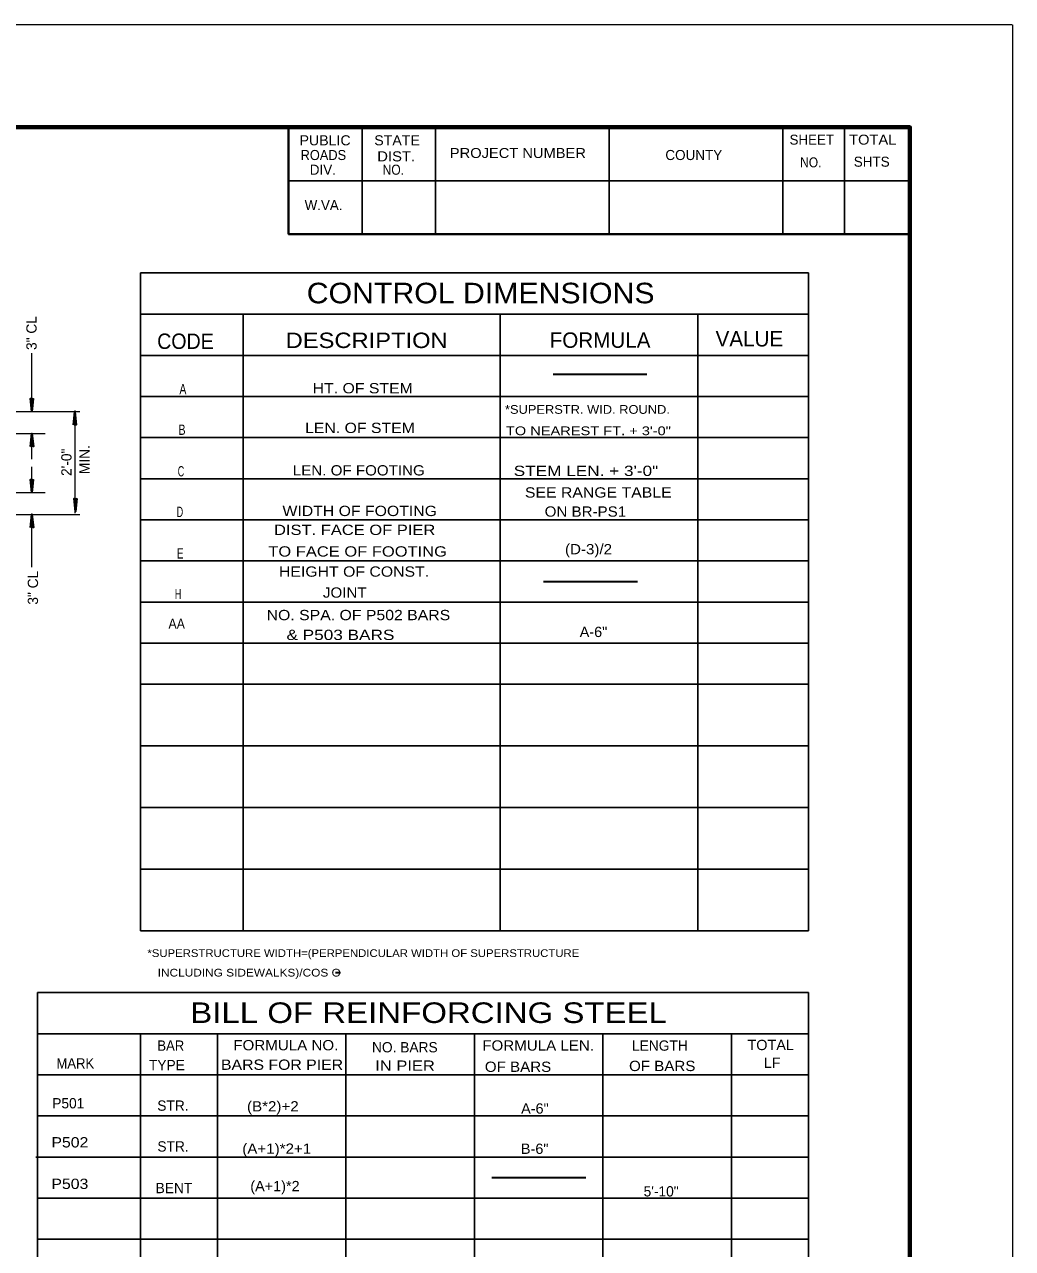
# Model space of a CAD drawing. Extents: x 4.49 to 7.69, y 0.28 to 2.27.
# Drawn here: x 6.888 to 7.689, y 1.277 to 2.269 of the extents above; entities that cross this region are included whole.
import ezdxf
from ezdxf.enums import TextEntityAlignment as Align

# ---------------------------------------------------------------- set-up
doc = ezdxf.new("R2010")
doc.units = 0
doc.header["$LTSCALE"] = 0.0033
doc.layers.add('1', color=7, linetype='Continuous', lineweight=35)

msp = doc.modelspace()

# ---------------------------------------------------------------- linework, layer by layer
at = {"layer": '1', "lineweight": 13}
for p, q in [((4.492417, 2.2695), (7.688833, 2.2695)), ((7.689083, 2.269333), (7.689083, 0.282917)), ((6.894083, 1.9655), (6.894083, 2.002917)), ((6.853333, 1.955583), (6.932833, 1.955583)), ((6.928833, 1.956583), (6.928833, 1.87325)), ((6.834917, 1.937917), (6.90475, 1.937917)), ((6.894083, 1.917), (6.894083, 1.937833)), ((6.894083, 1.889917), (6.894083, 1.91075)), ((6.83475, 1.889917), (6.90475, 1.889917)), ((6.853, 1.87225), (6.932833, 1.87225)), ((6.894083, 1.829583), (6.894083, 1.8705))]:
    msp.add_line(p, q, dxfattribs=at)
at = {"layer": '1', "lineweight": 25}
for p, q in [((7.161667, 2.186167), (7.161667, 2.0995)), ((7.22125, 2.186167), (7.22125, 2.0995)), ((7.362083, 2.186167), (7.362083, 2.0995)), ((7.502917, 2.186167), (7.502917, 2.0995)), ((7.55275, 2.186167), (7.55275, 2.0995)), ((7.102083, 2.142833), (7.605833, 2.142833)), ((6.982, 2.068), (6.982, 1.5345)), ((6.982, 2.068), (7.523667, 2.068)), ((7.523667, 2.068), (7.523667, 1.5345)), ((6.982, 2.0345), (7.523667, 2.0345)), ((7.065333, 2.0345), (7.065333, 1.5345)), ((7.273667, 2.0345), (7.273667, 1.5345)), ((7.434, 2.0345), (7.434, 1.5345)), ((6.982, 2.001167), (7.523667, 2.001167)), ((6.982, 1.967833), (7.523667, 1.967833)), ((6.982, 1.9345), (7.523667, 1.9345)), ((6.982, 1.901167), (7.523667, 1.901167)), ((6.982, 1.867833), (7.523667, 1.867833)), ((6.982, 1.8345), (7.523667, 1.8345)), ((6.982, 1.801167), (7.523667, 1.801167)), ((6.982, 1.767833), (7.523667, 1.767833)), ((6.982, 1.7345), (7.523667, 1.7345)), ((6.982, 1.6845), (7.523667, 1.6845)), ((6.982, 1.6345), (7.523667, 1.6345)), ((6.982, 1.5845), (7.523667, 1.5845)), ((6.982, 1.5345), (7.523667, 1.5345)), ((6.898667, 1.484667), (6.898667, 0.905417)), ((6.898667, 1.484667), (7.523667, 1.484667)), ((7.523667, 1.484667), (7.523667, 0.904)), ((6.898667, 1.451167), (7.523667, 1.451167)), ((6.982, 1.451167), (6.982, 0.904583)), ((7.0445, 1.451167), (7.0445, 0.905167)), ((7.148667, 1.451167), (7.148667, 0.905167)), ((7.252833, 1.451167), (7.252833, 0.905167)), ((7.357, 1.451167), (7.357, 0.904583)), ((7.461167, 1.451167), (7.461167, 0.904)), ((6.898667, 1.417833), (7.523667, 1.417833)), ((6.898667, 1.3845), (7.523667, 1.3845)), ((6.897167, 1.351167), (7.523667, 1.351167)), ((6.898667, 1.317833), (7.523667, 1.317833)), ((6.898667, 1.2845), (7.523667, 1.2845))]:
    msp.add_line(p, q, dxfattribs=at)
at = {"layer": '1'}
for p, q in [((7.316667, 1.986083), (7.392667, 1.986083)), ((6.893, 1.966), (6.893833, 1.958667)), ((6.893167, 1.966), (6.893917, 1.958667)), ((6.89325, 1.966), (6.894083, 1.958667)), ((6.893417, 1.966083), (6.894167, 1.95875)), ((6.894917, 1.966), (6.893917, 1.958167)), ((6.894083, 1.96625), (6.894083, 1.955667)), ((6.894917, 1.966), (6.894083, 1.958167)), ((6.895083, 1.966), (6.894167, 1.958167)), ((6.895083, 1.966), (6.894167, 1.958167)), ((6.895, 1.966), (6.894167, 1.958167)), ((6.928833, 1.945), (6.928833, 1.955583)), ((6.927833, 1.94525), (6.92875, 1.953083)), ((6.927833, 1.94525), (6.92875, 1.953083)), ((6.927917, 1.94525), (6.92875, 1.953083)), ((6.928, 1.94525), (6.928833, 1.953083)), ((6.928, 1.94525), (6.929, 1.953083)), ((6.9295, 1.945167), (6.92875, 1.9525)), ((6.929667, 1.94525), (6.928833, 1.952583)), ((6.92975, 1.94525), (6.929, 1.952583)), ((6.929917, 1.94525), (6.929083, 1.952583)), ((6.893083, 1.927583), (6.894, 1.935417)), ((6.893083, 1.927583), (6.894, 1.935417)), ((6.893167, 1.927583), (6.894, 1.935417)), ((6.89325, 1.927583), (6.894083, 1.935417)), ((6.89325, 1.927583), (6.89425, 1.935417)), ((6.894083, 1.927333), (6.894083, 1.937917)), ((6.89475, 1.9275), (6.894, 1.934833)), ((6.894917, 1.927583), (6.894083, 1.934917)), ((6.895, 1.927583), (6.89425, 1.934917)), ((6.895167, 1.927583), (6.894333, 1.934917)), ((6.893, 1.900333), (6.893833, 1.893)), ((6.893167, 1.900333), (6.893917, 1.893)), ((6.89325, 1.900333), (6.894083, 1.893)), ((6.893417, 1.900417), (6.894167, 1.893083)), ((6.894917, 1.900333), (6.893917, 1.8925)), ((6.894083, 1.900583), (6.894083, 1.89)), ((6.894917, 1.900333), (6.894083, 1.8925)), ((6.895083, 1.900333), (6.894167, 1.8925)), ((6.895083, 1.900333), (6.894167, 1.8925)), ((6.895, 1.900333), (6.894167, 1.8925)), ((6.928333, 1.884917), (6.929167, 1.877583)), ((6.9285, 1.884917), (6.92925, 1.877583)), ((6.928583, 1.884917), (6.929417, 1.877583)), ((6.92875, 1.885), (6.9295, 1.877667)), ((6.93025, 1.884917), (6.92925, 1.877083)), ((6.929417, 1.885167), (6.929417, 1.874583)), ((6.93025, 1.884917), (6.929417, 1.877083)), ((6.930417, 1.884917), (6.9295, 1.877083)), ((6.930417, 1.884917), (6.9295, 1.877083)), ((6.930333, 1.884917), (6.9295, 1.877083)), ((6.893083, 1.862), (6.894, 1.869833)), ((6.893083, 1.862), (6.894, 1.869833)), ((6.893167, 1.862), (6.894, 1.869833)), ((6.89325, 1.862), (6.894083, 1.869833)), ((6.89325, 1.862), (6.89425, 1.869833)), ((6.89475, 1.861917), (6.894, 1.86925)), ((6.894083, 1.86175), (6.894083, 1.872333)), ((6.894917, 1.862), (6.894083, 1.869333)), ((6.895, 1.862), (6.89425, 1.869333)), ((6.895167, 1.862), (6.894333, 1.869333)), ((7.308917, 1.817833), (7.384917, 1.817833)), ((7.140083, 1.500833), (7.144167, 1.500833)), ((7.267, 1.3345), (7.343, 1.3345))]:
    msp.add_line(p, q, dxfattribs=at)
at = {"layer": '1', "lineweight": 70}
msp.add_lwpolyline([(7.605833, 0.366083), (7.605833, 2.186167), (4.659167, 2.186167), (4.659167, 0.366083)], dxfattribs=at)
at = {"layer": '1', "lineweight": 40}
msp.add_lwpolyline([(7.102083, 2.186167), (7.102083, 2.0995), (7.605833, 2.0995)], dxfattribs=at)
at = {"layer": '1'}
for points in [[(6.895167, 1.96625), (6.894083, 1.955667), (6.892917, 1.96625), (6.894083, 1.965667)], [(6.894167, 1.9655), (6.89425, 1.960833), (6.894167, 1.960833), (6.894167, 1.96175), (6.89425, 1.9655), (6.894333, 1.9625), (6.894417, 1.965667), (6.8945, 1.963417), (6.894583, 1.965667), (6.894333, 1.962167), (6.894167, 1.9575), (6.893917, 1.958417), (6.893917, 1.957167), (6.893917, 1.9655), (6.89375, 1.963083), (6.89375, 1.965667), (6.894167, 1.960333), (6.8935, 1.965667)], [(6.92775, 1.945), (6.928833, 1.955583), (6.93, 1.945), (6.928833, 1.945583)], [(6.92875, 1.94575), (6.928667, 1.950417), (6.92875, 1.950417), (6.92875, 1.9495), (6.928667, 1.94575), (6.928583, 1.94875), (6.9285, 1.945583), (6.928417, 1.947833), (6.928333, 1.945583), (6.928583, 1.949083), (6.92875, 1.95375), (6.929, 1.952833), (6.929, 1.954083), (6.929, 1.94575), (6.929167, 1.948167), (6.929167, 1.945583), (6.92875, 1.950917), (6.929417, 1.945583)], [(6.893, 1.927333), (6.894083, 1.937917), (6.89525, 1.927333), (6.894083, 1.927917)], [(6.894, 1.928083), (6.893917, 1.93275), (6.894, 1.93275), (6.894, 1.931833), (6.893917, 1.928083), (6.893833, 1.931083), (6.89375, 1.927917), (6.893667, 1.930167), (6.893583, 1.927917), (6.893833, 1.931417), (6.894, 1.936083), (6.89425, 1.935167), (6.89425, 1.936417), (6.89425, 1.928083), (6.894417, 1.9305), (6.894417, 1.927917), (6.894, 1.93325), (6.894667, 1.927917)], [(6.895167, 1.900583), (6.894083, 1.89), (6.892917, 1.900583), (6.894083, 1.9)], [(6.894167, 1.899833), (6.89425, 1.895167), (6.894167, 1.895167), (6.894167, 1.896083), (6.89425, 1.899833), (6.894333, 1.896833), (6.894417, 1.9), (6.8945, 1.89775), (6.894583, 1.9), (6.894333, 1.8965), (6.894167, 1.891833), (6.893917, 1.89275), (6.893917, 1.8915), (6.893917, 1.899833), (6.89375, 1.897417), (6.89375, 1.9), (6.894167, 1.894667), (6.8935, 1.9)], [(6.9305, 1.885167), (6.929417, 1.874583), (6.92825, 1.885167), (6.929417, 1.884583)], [(6.9295, 1.884417), (6.929583, 1.87975), (6.9295, 1.87975), (6.9295, 1.880667), (6.929583, 1.884417), (6.929667, 1.881417), (6.92975, 1.884583), (6.929833, 1.882333), (6.929917, 1.884583), (6.929667, 1.881083), (6.9295, 1.876417), (6.92925, 1.877333), (6.92925, 1.876083), (6.92925, 1.884417), (6.929083, 1.882), (6.929083, 1.884583), (6.9295, 1.87925), (6.928833, 1.884583)], [(6.893, 1.86175), (6.894083, 1.872333), (6.89525, 1.86175), (6.894083, 1.862333)], [(6.894, 1.8625), (6.893917, 1.867167), (6.894, 1.867167), (6.894, 1.86625), (6.893917, 1.8625), (6.893833, 1.8655), (6.89375, 1.862333), (6.893667, 1.864583), (6.893583, 1.862333), (6.893833, 1.865833), (6.894, 1.8705), (6.89425, 1.869583), (6.89425, 1.870833), (6.89425, 1.8625), (6.894417, 1.864917), (6.894417, 1.862333), (6.894, 1.867667), (6.894667, 1.862333)]]:
    msp.add_lwpolyline(points, close=True, dxfattribs=at)
for points in [[(6.894167, 1.9655), (6.894917, 1.965917), (6.894667, 1.965667), (6.894333, 1.9655), (6.894417, 1.96525), (6.89475, 1.965417), (6.894, 1.965583), (6.8935, 1.96575), (6.893083, 1.966)], [(6.92875, 1.94575), (6.928, 1.945333), (6.92825, 1.945583), (6.928583, 1.94575), (6.9285, 1.946), (6.928167, 1.945833), (6.928917, 1.945667), (6.929417, 1.9455), (6.929833, 1.94525)], [(6.894, 1.928083), (6.89325, 1.927667), (6.8935, 1.927917), (6.893833, 1.928083), (6.89375, 1.928333), (6.893417, 1.928167), (6.894167, 1.928), (6.894667, 1.927833), (6.895083, 1.927583)], [(6.894167, 1.899833), (6.894917, 1.90025), (6.894667, 1.9), (6.894333, 1.899833), (6.894417, 1.899583), (6.89475, 1.89975), (6.894, 1.899917), (6.8935, 1.900083), (6.893083, 1.900333)], [(6.9295, 1.884417), (6.93025, 1.884833), (6.93, 1.884583), (6.929667, 1.884417), (6.92975, 1.884167), (6.930083, 1.884333), (6.929333, 1.8845), (6.928833, 1.884667), (6.928417, 1.884917)], [(6.894, 1.8625), (6.89325, 1.862083), (6.8935, 1.862333), (6.893833, 1.8625), (6.89375, 1.86275), (6.893417, 1.862583), (6.894167, 1.862417), (6.894667, 1.86225), (6.895083, 1.862)]]:
    msp.add_lwpolyline(points, dxfattribs=at)

# ---------------------------------------------------------------- texts
for s, height, width, p in [('PUBLIC', 0.008167, 1.05, (7.13175, 2.1715)), ('STATE', 0.008167, 1.05, (7.190083, 2.1715)), ('TOTAL', 0.008084, 1.1, (7.57575, 2.172083)), ('ROADS', 0.008167, 0.95, (7.130333, 2.159583)), ('DIST.', 0.008167, 1.1, (7.189375, 2.1585)), ('PROJECT NUMBER', 0.008084, 1.1, (7.288042, 2.16125)), ('NO.', 0.008167, 0.9, (7.187042, 2.147667)), ('NO.', 0.008084, 0.9, (7.525542, 2.153667)), ('HEIGHT OF CONST.', 0.008334, 1.15, (7.155208, 1.82175)), ('JOINT', 0.008334, 1.1, (7.147667, 1.80475)), ('AA', 0.008334, 0.9, (7.011417, 1.7795))]:
    msp.add_text(s, height=height, dxfattribs=dict(at, width=width)).set_placement(p, align=Align.CENTER)
for s, height, p in [('SHEET', 0.008084, (7.526333, 2.172083)), ('COUNTY', 0.008167, (7.430667, 2.159583)), ('DIV.', 0.008167, (7.129917, 2.147667)), ('SHTS', 0.008167, (7.574917, 2.154167)), ('W.VA.', 0.008084, (7.1305, 2.119))]:
    msp.add_text(s, height=height, dxfattribs=at).set_placement(p, align=Align.CENTER)
for s, height, width, p in [('CONTROL DIMENSIONS', 0.01667, 1.1, (7.116833, 2.043417)), ('CODE', 0.0125, 0.95, (6.995583, 2.006417)), ('DESCRIPTION ', 0.0125, 1.15, (7.09975, 2.007167)), ('A', 0.008334, 0.75, (7.013667, 1.96975)), ('HT. OF STEM', 0.008334, 1.15, (7.121667, 1.970417)), ('*SUPERSTR. WID. ROUND. ', 0.007083, 1.1, (7.277583, 1.953833)), ('LEN. OF STEM', 0.008334, 1.15, (7.1155, 1.93825)), ('B', 0.008334, 0.75, (7.013, 1.93675)), ('TO NEAREST FT. + 3\'-0"', 0.007083, 1.25, (7.278333, 1.9365)), ('C', 0.008334, 0.65, (7.01225, 1.903083)), ('LEN. OF FOOTING', 0.008334, 1.1, (7.105583, 1.903833)), ('STEM LEN. + 3\'-0"', 0.008334, 1.25, (7.284667, 1.903417)), ('SEE RANGE TABLE', 0.008334, 1.15, (7.29375, 1.885917)), ('D', 0.008334, 0.65, (7.011417, 1.870167)), ('WIDTH OF FOOTING', 0.008334, 1.15, (7.097167, 1.870917)), ('ON BR-PS1', 0.008334, 1.1, (7.30975, 1.870417)), ('DIST. FACE OF PIER', 0.008334, 1.2, (7.090333, 1.855583)), ('TO FACE OF FOOTING', 0.008334, 1.2, (7.085667, 1.838083)), ('(D-3)/2', 0.008334, 1.1, (7.32625, 1.839917)), ('E', 0.008334, 0.75, (7.011417, 1.8365)), ('H', 0.008334, 0.65, (7.009917, 1.803583)), ('NO. SPA. OF P502 BARS', 0.008334, 1.15, (7.084333, 1.7865)), ('& P503 BARS', 0.008334, 1.25, (7.100417, 1.770417)), ('A-6"', 0.008334, 1.05, (7.338167, 1.772833)), ('*SUPERSTRUCTURE WIDTH=(PERPENDICULAR WIDTH OF SUPERSTRUCTURE', 0.00625, 1.1, (6.987667, 1.513417)), ('INCLUDING SIDEWALKS)/COS O', 0.00625, 1.15, (6.996, 1.497583)), ('BILL OF REINFORCING STEEL', 0.01667, 1.2, (7.022417, 1.459917)), ('BAR', 0.008334, 0.95, (6.99575, 1.437417)), ('FORMULA NO.', 0.008334, 1.1, (7.057333, 1.43775)), ('FORMULA LEN.', 0.008334, 1.1, (7.259167, 1.4375)), ('TOTAL', 0.008334, 1.05, (7.474167, 1.437917)), ('MARK', 0.008334, 0.95, (6.913917, 1.423)), ('BARS FOR PIER', 0.008334, 1.15, (7.047333, 1.421917)), ('IN PIER', 0.008334, 1.2, (7.172417, 1.421167)), ('OF BARS', 0.008334, 1.1, (7.378167, 1.420917)), ('LF', 0.008334, 1.05, (7.487333, 1.4235)), ('OF BARS', 0.008334, 1.1, (7.26125, 1.42025)), ('(B*2)+2', 0.008334, 1.1, (7.068417, 1.388167)), ('A-6"', 0.008334, 1.05, (7.290667, 1.386417)), ('P502', 0.008334, 1.15, (6.909833, 1.359)), ('(A+1)*2+1', 0.008334, 1.1, (7.064583, 1.353833)), ('B-6"', 0.008334, 1.05, (7.2905, 1.35375)), ('P503', 0.008334, 1.15, (6.909833, 1.325333)), ('(A+1)*2', 0.008334, 1.05, (7.071083, 1.3235))]:
    msp.add_text(s, height=height, dxfattribs=dict(at, width=width)).set_placement(p)
for s, height, p in [('3" CL', 0.008334, (6.897833, 2.005583)), ('MIN.', 0.008334, (6.940833, 1.904917)), ('2\'-0"', 0.008333, (6.926167, 1.903417)), ('3" CL', 0.008334, (6.899, 1.799083))]:
    msp.add_text(s, height=height, rotation=90, dxfattribs=at).set_placement(p)
for s, height, p in [('FORMULA', 0.0125, (7.313833, 2.007333)), ('VALUE', 0.0125, (7.448333, 2.008417)), ('NO. BARS', 0.008334, (7.16975, 1.436083)), ('LENGTH', 0.008334, (7.380583, 1.437417)), ('TYPE', 0.008334, (6.988917, 1.421583)), ('P501', 0.008334, (6.9105, 1.390667)), ('STR.', 0.008334, (6.995667, 1.38875)), ('STR.', 0.008334, (6.99575, 1.355667)), ('BENT', 0.008334, (6.994333, 1.321917)), ('5\'-10"', 0.008334, (7.39, 1.31925))]:
    msp.add_text(s, height=height, dxfattribs=at).set_placement(p)

doc.saveas('drawing.dxf')
